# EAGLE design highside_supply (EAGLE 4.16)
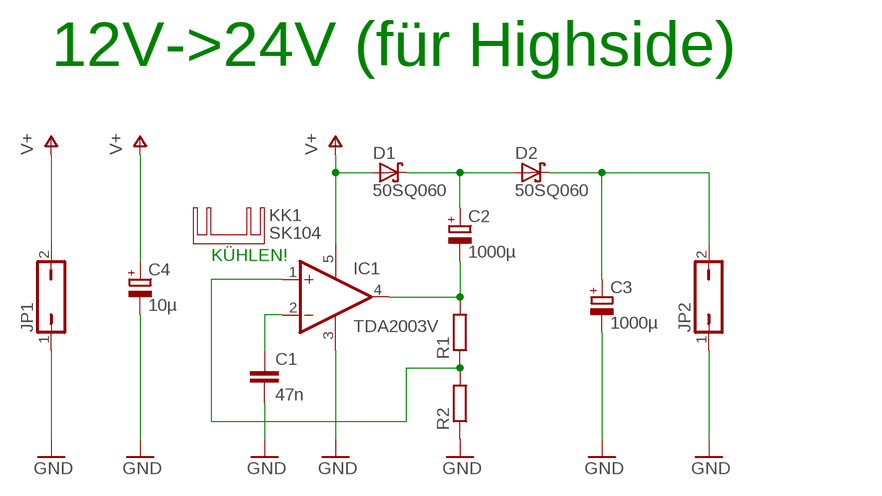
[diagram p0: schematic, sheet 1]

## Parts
C1  47n  C-EU050-025X075  [C050-025X075]
C2  1000µ  CPOL-EUE5-10.5  [E5-10,5]
C3  1000µ  CPOL-EUE5-10.5  [E5-10,5]
C4  10µ  CPOL-EUE5-10.5  [E5-10,5]
D1  50SQ060  15KEXXD  [DO201T15]
D2  50SQ060  15KEXXD  [DO201T15]
IC1  TDA2003V  [CB360]
JP1  JP1Q  [JP1]
JP2  JP1Q  [JP1]
KK1  SK104  [SK104]
R1  R-EU_0207/10  [0207/10]
R2  R-EU_0207/10  [0207/10]

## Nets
GND: C1.2 C3.- C4.- IC1.3(GND) JP1.1 JP2.1 R2.1
N$1: IC1.1(+IN) R1.1 R2.2
N$2: C2.- IC1.4(OUT) R1.2
N$3: C1.1 IC1.2(-IN)
N$5: C3.+ D2.C JP2.2
N$6: C2.+ D1.C D2.A
V+: C4.+ D1.A IC1.5(V+) JP1.2

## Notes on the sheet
- 12V->24V (für Highside)
- KÜHLEN!

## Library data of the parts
C1 = rcl:C-EU: CAPACITOR, European symbol
C2-C4 = rcl:CPOL-EU: POLARIZED CAPACITOR, European symbol
D1 D2 = diode:15KEXXD: DIODE
IC1 = linear:TDA2003: AUDIO AMPLIFIER
JP1 JP2 = jumper:JP1Q: JUMPER
KK1 = heatsink:SK104: HEATSINK
R1 R2 = rcl:R-EU_: RESISTOR, European symbol

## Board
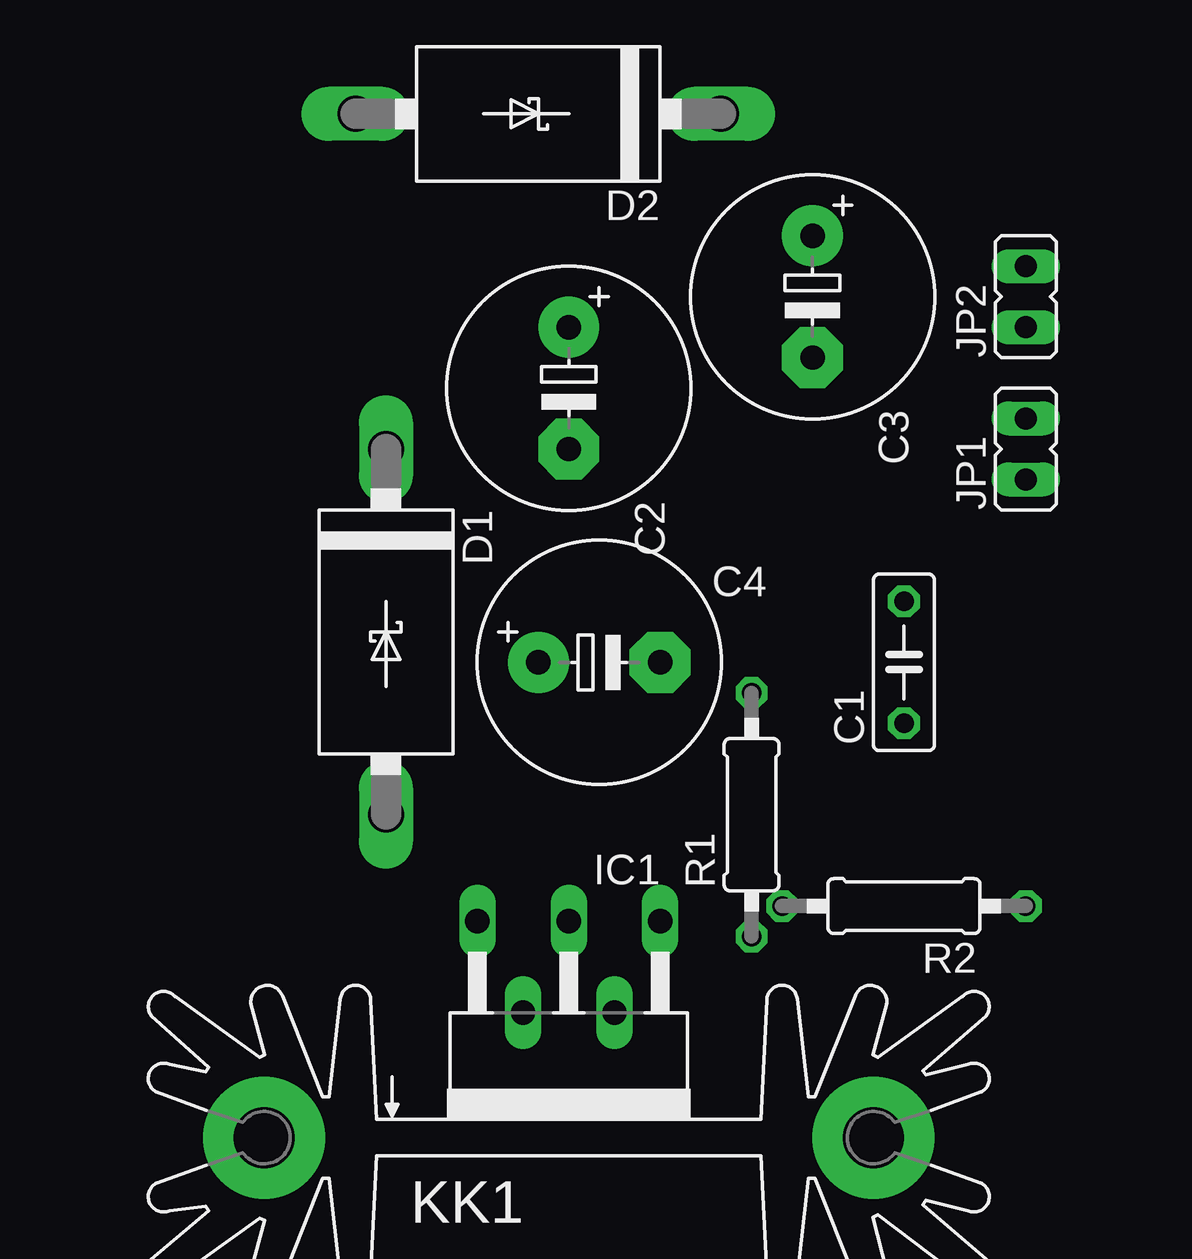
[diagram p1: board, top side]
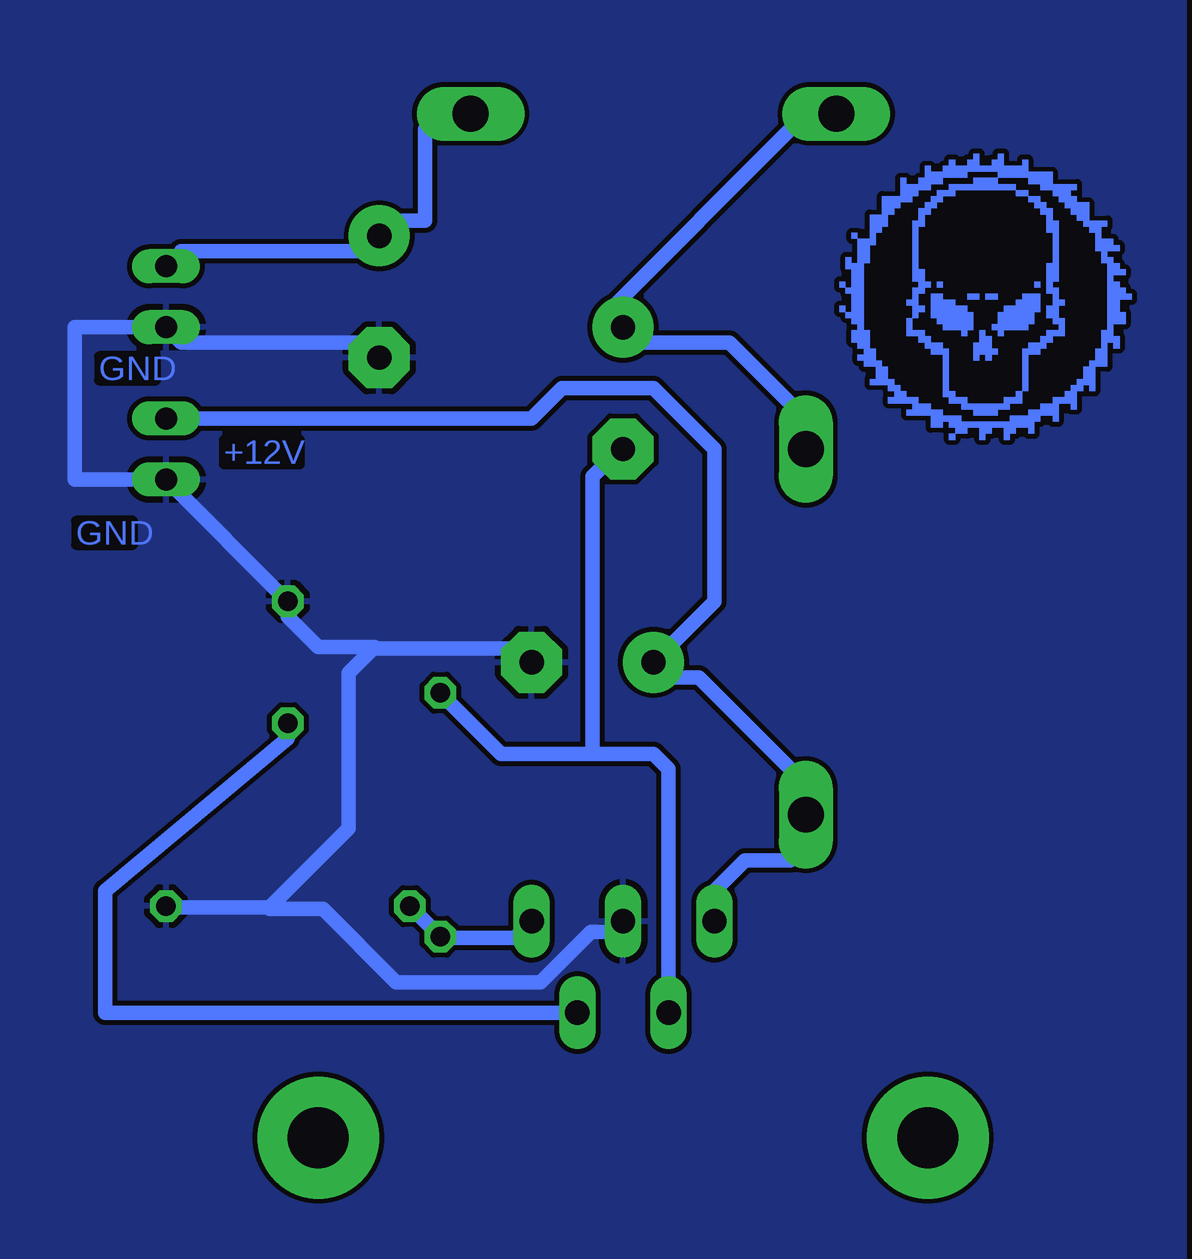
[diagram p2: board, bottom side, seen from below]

No outline drawn. Coordinates in mm, seen from the top.
Copper layers (1*16): Top 0.035mm / dielectric 1.5mm / Bottom 0.035mm
Design rules "default": minimum track width 10mil, minimum drill 24mil, track to track 8mil, track to pad 8mil, pad to pad 8mil, via to via 8mil, smd to smd 8mil, copper to edge 40mil, drill to drill 8mil, minimum pad ring 10mil, minimum via ring 8mil, stop-mask expansion 4mil, vias tented up to drill 0mil, thermal gap 10mil

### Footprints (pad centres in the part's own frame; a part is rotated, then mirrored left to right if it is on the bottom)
C050-025X075 = drill 0.813 octagon: 1 -2.54,0; 2 2.54,0
E5-10,5 = drill 1.016 pad 2.54 round: + -2.54,0 | drill 1.016 pad 2.54 octagon: - 2.54,0
DO201T15 = drill 1.499 long: A 7.62,0; C -7.62,0
CB360 = drill 1.016 long: 1 -3.81,-8.255; 2 -1.905,-4.445; 3 0,-8.255; 4 1.905,-4.445; 5 3.81,-8.255
JP1 = drill 0.914 long: 1 0,-1.27; 2 0,1.27
SK104 = drill 2.54 pad 5.08 round: A2,5 -12.7,-0.762; B2,5 12.7,-0.762
0207/10 = drill 0.813 octagon: 1 -5.08,0; 2 5.08,0

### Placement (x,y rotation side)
C1  35.56,29.21 90 top
C2  21.59,40.64 270 top
C3  31.75,44.45 270 top
C4  22.86,29.21 0 top
D1  13.97,30.48 270 top
D2  20.32,52.07 180 top
IC1  21.59,10.16 180 top
JP1  40.64,38.1 0 top
JP2  40.64,44.45 0 top
KK1  21.59,10.16 0 top
R1  29.21,22.86 90 top
R2  35.56,19.05 180 top

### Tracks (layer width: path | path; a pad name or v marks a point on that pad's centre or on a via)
GND
  Bottom 0.254: 35.56,31.11 C1.2
  Bottom 0.406: 31.94,29.84 26.04,29.84 C4.- 25.53,29.21 26.1,29.78 | 40.7,18.99 R2.1 | 31.88,29.78 32.96,28.7 32.96,22.29 36.32,18.92 | IC1.3 21.59,18.29
  Bottom 0.61: 35.56,31.11 34.29,29.84 31.94,29.84 33.02,28.77 33.02,22.29 36.32,18.99 40.7,18.99 | C1.2 JP1.1 44.45,36.83 44.45,43.18 JP2.1 40.01,42.55 32.38,42.55 C3.- 31.43,41.59 | 31.88,29.78 26.1,29.78 | 36.32,18.92 34.1,18.92 31.05,15.88 25.02,15.88 22.92,17.97 21.91,17.97 21.59,18.29
  pour Bottom: -1.78,54.86 -1.78,0.76 47.5,0.76 47.5,57.15 -1.78,57.15 -1.78,54.61 -1.78,53.59
N$1
  Bottom 0.406: 29.21,17.72 R1.1 | 30.61,18.92 30.67,18.92 | 30.61,18.92 R2.2 | 30.35,18.92 30.61,18.92
  Bottom 0.61: IC1.1 26.1,17.72 29.21,17.72 | R1.1 30.35,18.92
N$2
  Bottom 0.406: 21.72,38.1 C2.-
  Bottom 0.61: 22.86,25.4 20.32,25.4 19.68,24.77 IC1.4 | R1.2 26.67,25.4 22.86,25.4 | 22.86,25.4 22.86,36.96 21.72,38.1
N$3
  Bottom 0.61: IC1.2 43.18,14.61 43.18,19.68 35.56,26.04 C1.1
N$5
  Bottom 0.406: 40.01,46.35 JP2.2 | 31.11,47.62 C3.+
  Bottom 0.61: 40.01,46.35 32.38,46.35 C3.+ | 31.11,47.62 29.84,47.62 29.84,51.44 D2.C
N$6
  Bottom 0.254: 14.61,51.44 D2.A
  Bottom 0.61: D1.C 14.61,40.01 17.14,42.55 20.95,42.55 C2.+ 22.23,43.81 14.61,51.44
V+
  Bottom 0.254: D1.A 14.61,24.77
  Bottom 0.61: IC1.5 17.78,19.68 16.51,20.95 14.61,20.95 D1.A | 14.61,24.77 18.41,28.57 19.68,28.57 C4.+ 17.78,31.75 17.78,38.1 20.32,40.64 24.13,40.64 25.4,39.37 JP1.2
(copper drawn outside any net)
  shapes: Bottom area x206

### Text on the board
Bottom: GND | +12V | GND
